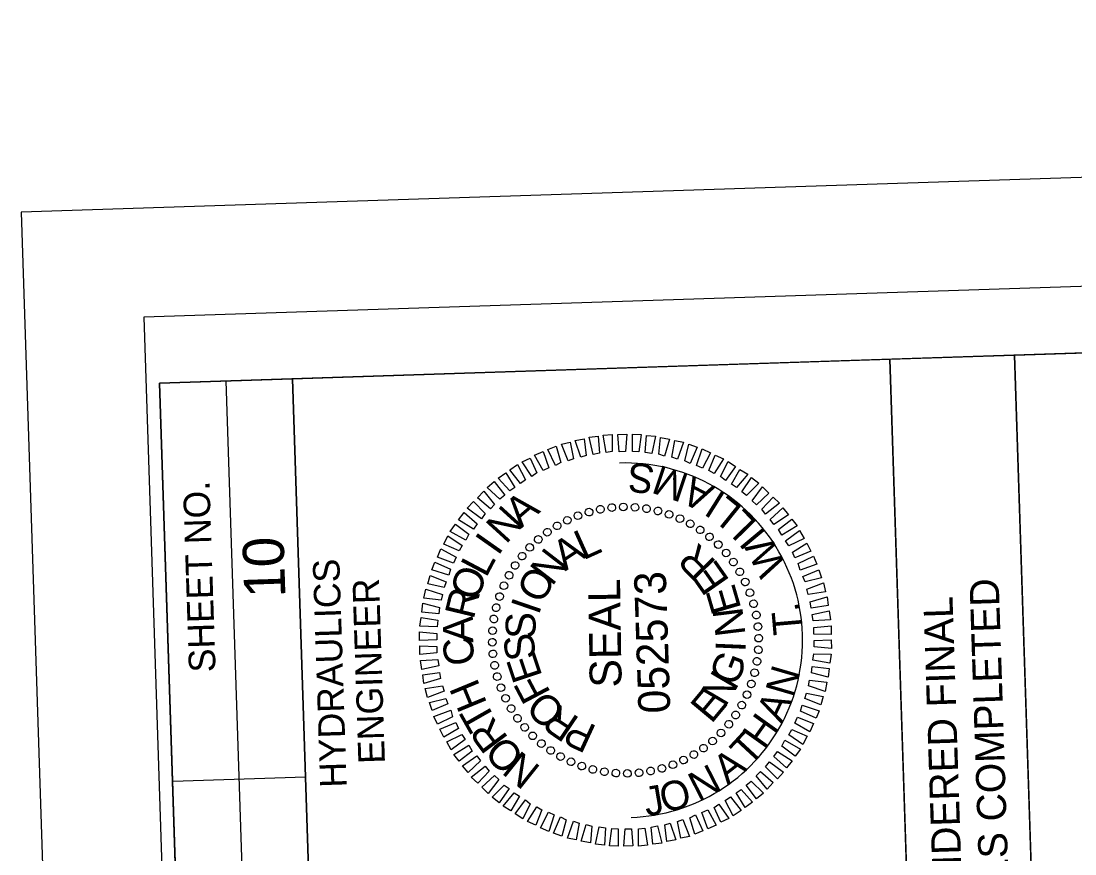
# Model space of a CAD drawing. Extents: x 1627314 to 1628469, y 762309 to 764247.
# Drawn here: x 1627314.2 to 1627512.6, y 763887.6 to 764044.4 of the extents above; entities that cross this region are included whole.
import ezdxf

# ---------------------------------------------------------------- set-up
doc = ezdxf.new("R2010")
doc.units = 0
for name, color, linetype in [('Old_Level_2', 7, 'Continuous'), ('Old_Level_58', 7, 'Continuous'), ('Scratch_Level_0', 7, 'Continuous'), ('Sheet Data Field CELL', 7, 'Continuous'), ('Sheet Plot Border Inside CELL', 7, 'Continuous'), ('Sheet Plot Border Outside CELL', 7, 'Continuous'), ('Sheet Professional Seal CELL', 7, 'Continuous'), ('Sheet Profile CELL', 7, 'Continuous'), ('Sheet Profile Grid Major CELL', 7, 'Continuous'), ('Sheet Profile Grid Minor CELL', 7, 'Continuous'), ('Sheet Sticker Exception Certification CELL', 7, 'Continuous')]:
    doc.layers.add(name, color=color, linetype=linetype)

msp = doc.modelspace()

# ---------------------------------------------------------------- linework, layer by layer
at = {"layer": 'Old_Level_2'}
msp.add_lwpolyline([(1627507.79, 763781.61), (1627501.25, 763981.49), (1627565.16, 763983.58), (1627571.7, 763783.7)], close=True, dxfattribs=at)
at = {"layer": 'Scratch_Level_0'}
msp.add_arc((1627428, 763927.84), 33.36, 271.8735, 91.8735, dxfattribs=at)
at = {"layer": 'Sheet Plot Border Inside CELL'}
msp.add_lwpolyline([(1628446.34, 762357.53), (1628391.86, 764023.14), (1627337.33, 763988.65), (1627391.81, 762323.04)], close=True, dxfattribs=at)
at = {"layer": 'Sheet Plot Border Outside CELL'}
msp.add_lwpolyline([(1628469.21, 762345.27), (1628413.63, 764044.37), (1627314.22, 764008.4), (1627369.79, 762309.31)], close=True, dxfattribs=at)
at = {"layer": 'Sheet Professional Seal CELL'}
for p, q in [((1627421.1, 763951.98), (1627421.1, 763951.98)), ((1627423.29, 763952.45), (1627423.29, 763952.45)), ((1627425.43, 763952.82), (1627425.43, 763952.82)), ((1627427.62, 763952.94), (1627427.62, 763952.94)), ((1627429.83, 763952.86), (1627429.83, 763952.86)), ((1627431.99, 763952.58), (1627431.99, 763952.58)), ((1627434.1, 763952.2), (1627434.1, 763952.2)), ((1627436.22, 763951.57), (1627436.22, 763951.57)), ((1627417.05, 763950.44), (1627417.05, 763950.44)), ((1627419.02, 763951.31), (1627419.02, 763951.31)), ((1627438.25, 763950.74), (1627438.25, 763950.74)), ((1627440.23, 763949.8), (1627440.23, 763949.8)), ((1627413.27, 763948.17), (1627413.27, 763948.17)), ((1627415.13, 763949.38), (1627415.13, 763949.38)), ((1627442.07, 763948.61), (1627442.07, 763948.61)), ((1627411.56, 763946.86), (1627411.56, 763946.86)), ((1627443.87, 763947.32), (1627443.87, 763947.32)), ((1627445.47, 763945.87), (1627445.47, 763945.87)), ((1627408.52, 763943.71), (1627408.52, 763943.71)), ((1627409.96, 763945.31), (1627409.96, 763945.31)), ((1627447.02, 763944.27), (1627447.02, 763944.27)), ((1627407.22, 763941.92), (1627407.22, 763941.92)), ((1627448.33, 763942.56), (1627448.33, 763942.56)), ((1627406.03, 763940.08), (1627406.03, 763940.08)), ((1627449.54, 763940.7), (1627449.54, 763940.7)), ((1627405.1, 763938.1), (1627405.1, 763938.1)), ((1627450.6, 763938.78), (1627450.6, 763938.78)), ((1627404.26, 763936.07), (1627404.26, 763936.07)), ((1627451.46, 763936.81), (1627451.46, 763936.81)), ((1627403.63, 763933.95), (1627403.63, 763933.95)), ((1627452.13, 763934.73), (1627452.13, 763934.73)), ((1627403.25, 763931.83), (1627403.25, 763931.83)), ((1627452.6, 763932.55), (1627452.6, 763932.55)), ((1627402.97, 763929.67), (1627402.97, 763929.67)), ((1627452.98, 763930.41), (1627452.98, 763930.41)), ((1627428, 763927.84), (1627428, 763927.84)), ((1627453.1, 763928.21), (1627453.1, 763928.21)), ((1627402.89, 763927.47), (1627402.89, 763927.47)), ((1627453.02, 763926.01), (1627453.02, 763926.01)), ((1627403.02, 763925.27), (1627403.02, 763925.27)), ((1627452.74, 763923.85), (1627452.74, 763923.85)), ((1627403.39, 763923.13), (1627403.39, 763923.13)), ((1627452.36, 763921.73), (1627452.36, 763921.73)), ((1627403.86, 763920.95), (1627403.86, 763920.95)), ((1627404.53, 763918.87), (1627404.53, 763918.87)), ((1627451.73, 763919.61), (1627451.73, 763919.61)), ((1627405.39, 763916.89), (1627405.39, 763916.89)), ((1627450.89, 763917.58), (1627450.89, 763917.58)), ((1627406.45, 763914.98), (1627406.45, 763914.98)), ((1627448.77, 763913.76), (1627448.77, 763913.76)), ((1627449.96, 763915.6), (1627449.96, 763915.6)), ((1627407.67, 763913.12), (1627407.67, 763913.12)), ((1627447.47, 763911.97), (1627447.47, 763911.97)), ((1627408.97, 763911.41), (1627408.97, 763911.41)), ((1627410.53, 763909.81), (1627410.53, 763909.81)), ((1627446.03, 763910.37), (1627446.03, 763910.37)), ((1627412.12, 763908.36), (1627412.12, 763908.36)), ((1627444.43, 763908.82), (1627444.43, 763908.82)), ((1627413.92, 763907.07), (1627413.92, 763907.07)), ((1627415.76, 763905.88), (1627415.76, 763905.88)), ((1627440.86, 763906.3), (1627440.86, 763906.3)), ((1627442.72, 763907.51), (1627442.72, 763907.51)), ((1627417.74, 763904.94), (1627417.74, 763904.94)), ((1627419.77, 763904.11), (1627419.77, 763904.11)), ((1627436.97, 763904.37), (1627436.97, 763904.37)), ((1627438.94, 763905.23), (1627438.94, 763905.23)), ((1627421.89, 763903.48), (1627421.89, 763903.48)), ((1627424, 763903.09), (1627424, 763903.09)), ((1627426.16, 763902.82), (1627426.16, 763902.82)), ((1627428.37, 763902.74), (1627428.37, 763902.74)), ((1627430.56, 763902.86), (1627430.56, 763902.86)), ((1627432.7, 763903.23), (1627432.7, 763903.23)), ((1627434.89, 763903.7), (1627434.89, 763903.7))]:
    msp.add_line(p, q, dxfattribs=at)
for points in [[(1627419.57, 763962.28), (1627418.51, 763965.4), (1627420.2, 763965.75), (1627420.6, 763962.62)], [(1627421.95, 763962.81), (1627421.14, 763966.03), (1627422.84, 763966.24), (1627423.14, 763963.05)], [(1627424.34, 763963.19), (1627423.83, 763966.42), (1627425.53, 763966.58), (1627425.53, 763963.33)], [(1627426.84, 763963.32), (1627426.58, 763966.56), (1627428.28, 763966.62), (1627428.03, 763963.36)], [(1627429.34, 763963.35), (1627429.33, 763966.6), (1627430.98, 763966.56), (1627430.54, 763963.29)], [(1627431.74, 763963.18), (1627431.94, 763966.39), (1627433.64, 763966.24), (1627432.95, 763962.97)], [(1627434.3, 763962.86), (1627434.6, 763965.97), (1627436.31, 763965.68), (1627435.37, 763962.5)], [(1627436.72, 763962.29), (1627437.27, 763965.41), (1627438.93, 763965.12), (1627437.79, 763961.93)], [(1627412.49, 763959.75), (1627410.9, 763962.65), (1627412.48, 763963.35), (1627413.58, 763960.28)], [(1627414.81, 763960.72), (1627413.41, 763963.73), (1627414.95, 763964.33), (1627415.85, 763961.26)], [(1627417.19, 763961.6), (1627415.93, 763964.76), (1627417.57, 763965.12), (1627418.22, 763961.99)], [(1627439.15, 763961.62), (1627439.95, 763964.75), (1627441.52, 763964.15), (1627440.21, 763961.11)], [(1627441.38, 763960.69), (1627442.43, 763963.83), (1627444, 763963.13), (1627442.49, 763960.23)], [(1627410.38, 763958.68), (1627408.54, 763961.42), (1627410.07, 763962.12), (1627411.31, 763959.31)], [(1627443.71, 763959.77), (1627444.87, 763962.66), (1627446.44, 763961.96), (1627444.68, 763959.2)], [(1627445.9, 763958.64), (1627447.31, 763961.49), (1627448.74, 763960.53), (1627446.82, 763957.87)], [(1627408.22, 763957.31), (1627406.24, 763959.89), (1627407.7, 763960.89), (1627409.2, 763958.04)], [(1627447.95, 763957.21), (1627449.56, 763959.96), (1627451.04, 763959.06), (1627448.92, 763956.59)], [(1627404.32, 763954.38), (1627401.99, 763956.6), (1627403.31, 763957.7), (1627405.29, 763955.11)], [(1627406.22, 763955.94), (1627404.04, 763958.32), (1627405.45, 763959.32), (1627407.15, 763956.57)], [(1627449.89, 763955.77), (1627451.76, 763958.43), (1627453.09, 763957.37), (1627450.82, 763955.1)], [(1627402.57, 763952.57), (1627400.15, 763954.64), (1627401.31, 763955.88), (1627403.35, 763953.35)], [(1627451.85, 763954.08), (1627453.82, 763956.7), (1627455.01, 763955.49), (1627452.68, 763953.31)], [(1627400.88, 763950.71), (1627398.22, 763952.68), (1627399.38, 763953.92), (1627401.6, 763951.69)], [(1627453.65, 763952.49), (1627455.78, 763954.76), (1627457.02, 763953.6), (1627454.38, 763951.56)], [(1627399.4, 763948.76), (1627396.59, 763950.52), (1627397.64, 763951.86), (1627400.06, 763949.74)], [(1627455.27, 763950.54), (1627457.6, 763952.77), (1627458.69, 763951.45), (1627455.95, 763949.61)], [(1627397.96, 763946.67), (1627395.01, 763948.32), (1627396.02, 763949.65), (1627398.53, 763947.79)], [(1627456.83, 763948.69), (1627459.32, 763950.62), (1627460.31, 763949.36), (1627457.46, 763947.61)], [(1627396.68, 763944.67), (1627393.79, 763945.93), (1627394.59, 763947.46), (1627397.25, 763945.64)], [(1627458.15, 763946.53), (1627460.79, 763948.47), (1627461.64, 763946.95), (1627458.78, 763945.6)], [(1627459.42, 763944.42), (1627462.17, 763946.12), (1627462.92, 763944.59), (1627459.91, 763943.34)], [(1627395.6, 763942.34), (1627392.62, 763943.49), (1627393.26, 763945.06), (1627396.12, 763943.45)], [(1627460.54, 763942.26), (1627463.4, 763943.65), (1627464.05, 763942.17), (1627460.88, 763941.02)], [(1627394.73, 763940.06), (1627391.54, 763941.1), (1627392.1, 763942.52), (1627395.04, 763941.22)], [(1627393.9, 763937.78), (1627390.78, 763938.43), (1627391.23, 763939.99), (1627394.22, 763938.84)], [(1627461.42, 763939.84), (1627464.38, 763941.08), (1627464.88, 763939.55), (1627461.81, 763938.8)], [(1627462.15, 763937.46), (1627465.26, 763938.61), (1627465.67, 763936.92), (1627462.43, 763936.42)], [(1627393.33, 763935.36), (1627390.07, 763935.75), (1627390.41, 763937.46), (1627393.55, 763936.42)], [(1627462.78, 763935.08), (1627465.95, 763935.98), (1627466.15, 763934.34), (1627462.97, 763933.88)], [(1627392.86, 763932.79), (1627389.65, 763933.14), (1627389.85, 763934.79), (1627392.98, 763934)], [(1627392.54, 763930.38), (1627389.29, 763930.47), (1627389.53, 763932.13), (1627392.7, 763931.59)], [(1627463.16, 763932.69), (1627466.34, 763933.34), (1627466.59, 763931.65), (1627463.34, 763931.5)], [(1627463.49, 763930.2), (1627466.73, 763930.56), (1627466.73, 763928.91), (1627463.48, 763929)], [(1627392.48, 763927.88), (1627389.23, 763927.77), (1627389.22, 763929.42), (1627392.49, 763929.08)], [(1627463.52, 763927.8), (1627466.76, 763927.91), (1627466.77, 763926.26), (1627463.51, 763926.6)], [(1627392.5, 763925.48), (1627389.26, 763925.12), (1627389.26, 763926.77), (1627392.51, 763926.68)], [(1627392.84, 763922.99), (1627389.66, 763922.33), (1627389.4, 763924.02), (1627392.65, 763924.18)], [(1627463.45, 763925.3), (1627466.7, 763925.2), (1627466.46, 763923.54), (1627463.29, 763924.09)], [(1627393.21, 763920.6), (1627390.04, 763919.69), (1627389.84, 763921.34), (1627393.02, 763921.79)], [(1627463.13, 763922.88), (1627466.34, 763922.54), (1627466.14, 763920.88), (1627463.02, 763921.68)], [(1627462.66, 763920.32), (1627465.92, 763919.92), (1627465.58, 763918.21), (1627462.44, 763919.26)], [(1627393.84, 763918.22), (1627390.73, 763917.06), (1627390.32, 763918.75), (1627393.56, 763919.26)], [(1627462.09, 763917.9), (1627465.21, 763917.25), (1627464.76, 763915.68), (1627461.77, 763916.84)], [(1627394.57, 763915.84), (1627391.61, 763914.59), (1627391.11, 763916.13), (1627394.19, 763916.88)], [(1627395.45, 763913.42), (1627392.59, 763912.02), (1627391.95, 763913.5), (1627395.11, 763914.66)], [(1627461.26, 763915.62), (1627464.45, 763914.57), (1627463.89, 763913.15), (1627460.95, 763914.46)], [(1627396.57, 763911.25), (1627393.82, 763909.56), (1627393.07, 763911.09), (1627396.09, 763912.34)], [(1627460.39, 763913.34), (1627463.38, 763912.19), (1627462.73, 763910.61), (1627459.87, 763912.22)], [(1627397.84, 763909.14), (1627395.2, 763907.21), (1627394.35, 763908.73), (1627397.21, 763910.07)], [(1627459.31, 763911), (1627462.21, 763909.75), (1627461.4, 763908.22), (1627458.74, 763910.03)], [(1627399.16, 763906.98), (1627396.67, 763905.05), (1627395.68, 763906.32), (1627398.53, 763908.06)], [(1627458.03, 763909.01), (1627460.98, 763907.36), (1627459.98, 763906.02), (1627457.46, 763907.89)], [(1627400.72, 763905.13), (1627398.39, 763902.91), (1627397.3, 763904.22), (1627400.04, 763906.06)], [(1627456.6, 763906.91), (1627459.4, 763905.15), (1627458.35, 763903.82), (1627455.93, 763905.94)], [(1627402.34, 763903.19), (1627400.21, 763900.92), (1627398.97, 763902.08), (1627401.61, 763904.11)], [(1627455.11, 763904.96), (1627457.77, 763903), (1627456.61, 763901.76), (1627454.39, 763903.99)], [(1627404.14, 763901.59), (1627402.18, 763898.98), (1627400.99, 763900.19), (1627403.32, 763902.37)], [(1627453.42, 763903.11), (1627455.84, 763901.03), (1627454.68, 763899.8), (1627452.64, 763902.33)], [(1627406.1, 763899.91), (1627404.23, 763897.25), (1627402.9, 763898.3), (1627405.17, 763900.58)], [(1627451.68, 763901.3), (1627454, 763899.07), (1627452.68, 763897.98), (1627450.7, 763900.57)], [(1627408.05, 763898.47), (1627406.43, 763895.72), (1627404.95, 763896.62), (1627407.07, 763899.09)], [(1627447.77, 763898.37), (1627449.76, 763895.78), (1627448.29, 763894.78), (1627446.79, 763897.64)], [(1627449.78, 763899.74), (1627451.95, 763897.36), (1627450.54, 763896.36), (1627448.85, 763899.1)], [(1627410.09, 763897.04), (1627408.69, 763894.19), (1627407.25, 763895.14), (1627409.17, 763897.81)], [(1627412.28, 763895.91), (1627411.12, 763893.02), (1627409.55, 763893.72), (1627411.31, 763896.48)], [(1627443.5, 763895.93), (1627445.09, 763893.03), (1627443.51, 763892.33), (1627442.41, 763895.39)], [(1627445.61, 763897), (1627447.45, 763894.26), (1627445.93, 763893.56), (1627444.68, 763896.37)], [(1627414.61, 763894.98), (1627413.56, 763891.85), (1627411.99, 763892.55), (1627413.5, 763895.45)], [(1627416.84, 763894.06), (1627416.05, 763890.93), (1627414.48, 763891.53), (1627415.78, 763894.57)], [(1627438.81, 763894.07), (1627440.06, 763890.91), (1627438.42, 763890.56), (1627437.77, 763893.69)], [(1627441.18, 763894.95), (1627442.58, 763891.95), (1627441.05, 763891.35), (1627440.14, 763894.42)], [(1627419.27, 763893.38), (1627418.72, 763890.26), (1627417.06, 763890.56), (1627418.2, 763893.75)], [(1627421.69, 763892.81), (1627421.39, 763889.7), (1627419.68, 763890), (1627420.62, 763893.18)], [(1627424.25, 763892.5), (1627424.05, 763889.29), (1627422.35, 763889.43), (1627423.04, 763892.71)], [(1627426.66, 763892.33), (1627426.66, 763889.07), (1627425.01, 763889.12), (1627425.45, 763892.39)], [(1627429.16, 763892.36), (1627429.41, 763889.11), (1627427.71, 763889.06), (1627427.96, 763892.32)], [(1627431.65, 763892.49), (1627432.16, 763889.25), (1627430.46, 763889.1), (1627430.46, 763892.35)], [(1627434.04, 763892.87), (1627434.85, 763889.64), (1627433.15, 763889.44), (1627432.85, 763892.63)], [(1627436.43, 763893.4), (1627437.48, 763890.28), (1627435.79, 763889.92), (1627435.39, 763893.06)]]:
    msp.add_lwpolyline(points, close=True, dxfattribs=at)
for centre, major_axis in [((1627425.43, 763952.79), (-0.074, 0.716)), ((1627427.61, 763952.92), (-0.011, 0.72)), ((1627429.8, 763952.85), (0.052, 0.718)), ((1627419.06, 763951.27), (-0.257, 0.673)), ((1627421.14, 763951.96), (-0.197, 0.693)), ((1627423.26, 763952.47), (-0.136, 0.707)), ((1627431.97, 763952.6), (0.114, 0.711)), ((1627434.12, 763952.16), (0.176, 0.698)), ((1627436.21, 763951.53), (0.236, 0.68)), ((1627438.25, 763950.73), (0.294, 0.657)), ((1627415.13, 763949.36), (-0.369, 0.618)), ((1627417.05, 763950.4), (-0.314, 0.648)), ((1627440.2, 763949.75), (0.35, 0.629)), ((1627411.58, 763946.8), (-0.471, 0.544)), ((1627413.3, 763948.16), (-0.422, 0.583)), ((1627442.07, 763948.6), (0.404, 0.596)), ((1627443.82, 763947.29), (0.454, 0.559)), ((1627409.99, 763945.3), (-0.517, 0.501)), ((1627445.46, 763945.84), (0.501, 0.517)), ((1627408.54, 763943.66), (-0.559, 0.454)), ((1627446.96, 763944.25), (0.544, 0.471)), ((1627407.23, 763941.91), (-0.596, 0.404)), ((1627448.32, 763942.54), (0.583, 0.422)), ((1627449.52, 763940.71), (0.618, 0.369)), ((1627406.09, 763940.05), (-0.629, 0.35)), ((1627450.56, 763938.78), (0.648, 0.314)), ((1627405.11, 763938.09), (-0.657, 0.294)), ((1627451.43, 763936.77), (0.673, 0.257)), ((1627404.3, 763936.06), (-0.68, 0.236)), ((1627403.67, 763933.96), (-0.698, 0.176)), ((1627452.12, 763934.7), (0.693, 0.197)), ((1627403.23, 763931.82), (-0.711, 0.114)), ((1627452.63, 763932.57), (0.707, 0.136)), ((1627402.98, 763929.64), (-0.718, 0.052)), ((1627452.94, 763930.4), (0.716, 0.074)), ((1627402.92, 763927.46), (-0.72, -0.011)), ((1627453.07, 763928.22), (0.72, 0.011)), ((1627403.05, 763925.27), (-0.716, -0.074)), ((1627453.01, 763926.03), (0.718, -0.052)), ((1627403.37, 763923.11), (-0.707, -0.136)), ((1627452.76, 763923.86), (0.711, -0.114)), ((1627403.87, 763920.98), (-0.693, -0.197)), ((1627452.32, 763921.72), (0.698, -0.176)), ((1627404.56, 763918.9), (-0.673, -0.257)), ((1627451.69, 763919.62), (0.68, -0.236)), ((1627405.43, 763916.89), (-0.648, -0.314)), ((1627450.88, 763917.59), (0.657, -0.294)), ((1627406.47, 763914.97), (-0.618, -0.369)), ((1627449.9, 763915.63), (0.629, -0.35)), ((1627407.67, 763913.14), (-0.583, -0.422)), ((1627448.76, 763913.77), (0.596, -0.404)), ((1627409.03, 763911.43), (-0.544, -0.471)), ((1627447.45, 763912.01), (0.559, -0.454)), ((1627410.53, 763909.84), (-0.501, -0.517)), ((1627446, 763910.38), (0.517, -0.501)), ((1627412.17, 763908.38), (-0.454, -0.559)), ((1627413.93, 763907.08), (-0.404, -0.596)), ((1627442.69, 763907.52), (0.422, -0.583)), ((1627444.41, 763908.87), (0.471, -0.544)), ((1627415.79, 763905.93), (-0.35, -0.629)), ((1627438.94, 763905.27), (0.314, -0.648)), ((1627440.87, 763906.31), (0.369, -0.618)), ((1627417.74, 763904.95), (-0.294, -0.657)), ((1627419.78, 763904.14), (-0.236, -0.68)), ((1627421.87, 763903.52), (-0.176, -0.698)), ((1627424.02, 763903.08), (-0.114, -0.711)), ((1627432.73, 763903.21), (0.136, -0.707)), ((1627434.86, 763903.71), (0.197, -0.693)), ((1627436.93, 763904.4), (0.257, -0.673)), ((1627426.19, 763902.82), (-0.052, -0.718)), ((1627428.38, 763902.76), (0.011, -0.72)), ((1627430.56, 763902.89), (0.074, -0.716))]:
    msp.add_ellipse(centre, major_axis=major_axis, ratio=0.999708, dxfattribs=at)
at = {"layer": 'Sheet Profile CELL'}
for p, q in [((1627359.37, 763776.71), (1627352.83, 763976.65)), ((1627342.78, 763901.28), (1627367.77, 763902.1))]:
    msp.add_line(p, q, dxfattribs=at)
for points in [[(1627340.28, 763976.24), (1627389.32, 762477.04), (1628438.76, 762511.37), (1628389.72, 764010.57)], [(1627368.59, 763877.11), (1627365.32, 763977.06), (1627477.76, 763980.74), (1627481.03, 763880.79)], [(1627346.82, 763776.3), (1627340.28, 763976.24), (1627365.32, 763977.06), (1627371.86, 763777.12)]]:
    msp.add_lwpolyline(points, close=True, dxfattribs=at)
at = {"layer": 'Sheet Profile Grid Major CELL'}
msp.add_lwpolyline([(1627566.8, 763933.62), (1627841.65, 763942.61), (1627840.02, 763992.59), (1627490.2, 763981.14)], dxfattribs=at)
at = {"layer": 'Sheet Sticker Exception Certification CELL'}
for p, q in [((1627477.77, 763980.72), (1627501.26, 763981.49)), ((1627477.77, 763980.72), (1627501.26, 763981.49)), ((1627501.25, 763981.49), (1627507.79, 763781.56)), ((1627501.25, 763981.49), (1627507.79, 763781.56)), ((1627484.3, 763780.79), (1627477.76, 763980.72)), ((1627484.3, 763780.79), (1627477.76, 763980.72))]:
    msp.add_line(p, q, dxfattribs=at)

# ---------------------------------------------------------------- texts
at = {"layer": 'Old_Level_58'}
for s, rotation, p in [('S', 173.0617, (1627433.71, 763960.75)), ('M', 161.4413, (1627440.22, 763958.93)), ('A', 152.311, (1627445, 763956.6)), ('I', 147.846, (1627447.18, 763955.18)), ('L', 141.0913, (1627450.27, 763952.74)), ('L', 134.3366, (1627453.04, 763949.94)), ('I', 129.8716, (1627454.69, 763947.93)), ('W', 117.321, (1627458.41, 763941.65)), ('.', 102.2517, (1627460.96, 763933.26)), ('T', 95.0104, (1627461.38, 763929.07)), ('N', 73.7445, (1627459.55, 763916.87)), ('A', 64.6142, (1627457.41, 763912.01)), ('H', 54.4249, (1627454.15, 763907.05)), ('T', 47.1836, (1627451.32, 763903.92)), ('A', 38.0533, (1627447.23, 763900.52)), ('N', 27.1771, (1627441.73, 763897.38)), ('J', 9.715, (1627431.96, 763894.67)), ('O', 15.528, (1627435.3, 763895.24))]:
    msp.add_text(s, height=5.5, rotation=rotation, dxfattribs=at).set_placement(p)
at = {"layer": 'Sheet Data Field CELL'}
msp.add_text('10', height=7.75, rotation=91.8735, dxfattribs=at).set_placement((1627364, 763935.91))
at = {"layer": 'Sheet Professional Seal CELL'}
for s, height, rotation, p in [('A', 5.64, 40.4906, (1627408.35, 763948.81)), ('N', 5.64, 47.6924, (1627405.5, 763945.76)), ('I', 5.64, 54.8936, (1627404.02, 763943.56)), ('L', 5.64, 24.2743, (1627420.05, 763942.84)), ('A', 5.64, 33.6337, (1627416.67, 763940.77)), ('R', 5.64, 134.3549, (1627445.28, 763942.51)), ('N', 5.64, 52.3501, (1627414.16, 763937.84)), ('L', 5.64, 62.0943, (1627401.75, 763939.44)), ('E', 5.64, 124.9976, (1627447.74, 763939.04)), ('O', 5.64, 69.2946, (1627400.05, 763934.98)), ('O', 5.64, 61.707, (1627412.27, 763934.43)), ('SEAL', 5.998, 90.8735, (1627427.29, 763918.96)), ('E', 5.64, 106.2852, (1627449.86, 763933.81)), ('R', 5.64, 76.4946, (1627399.41, 763931.61)), ('I', 5.64, 71.0631, (1627411.64, 763932.41)), ('N', 5.64, 96.9299, (1627450.62, 763928.88)), ('A', 5.64, 90.8938, (1627399.34, 763927.4)), ('S', 5.64, 89.7739, (1627411.08, 763928.09)), ('C', 5.64, 98.0933, (1627399.77, 763923.46)), ('S', 5.64, 99.1291, (1627411.25, 763924.49)), ('I', 5.64, 87.5747, (1627450.58, 763925.53)), ('E', 5.64, 108.4845, (1627412.41, 763921.08)), ('G', 5.64, 68.8637, (1627448.9, 763918.92)), ('N', 5.64, 59.5074, (1627446.77, 763915.05)), ('H', 5.64, 112.4929, (1627402.02, 763915.93)), ('F', 5.64, 117.8405, (1627414.01, 763917.93)), ('E', 5.64, 50.1504, (1627444.17, 763911.96)), ('O', 5.64, 136.5547, (1627417.07, 763914.72)), ('R', 5.64, 145.9131, (1627419.57, 763913.06)), ('T', 5.64, 119.6932, (1627403.78, 763912.74)), ('R', 5.64, 126.894, (1627406.09, 763909.41)), ('P', 5.64, 155.2724, (1627422.83, 763911.56)), ('O', 5.64, 134.0952, (1627409.3, 763906.07)), ('N', 5.64, 141.297, (1627412.27, 763903.86))]:
    msp.add_text(s, height=height, rotation=rotation, dxfattribs=at).set_placement(p)
at = {"layer": 'Sheet Profile CELL'}
for s, p in [('SHEET NO.', (1627350.85, 763921.87)), ('HYDRAULICS', (1627375.53, 763900.16)), ('ENGINEER', (1627382.73, 763904.65))]:
    msp.add_text(s, height=5, rotation=91.8735, dxfattribs=at).set_placement(p)
at = {"layer": 'Sheet Profile Grid Minor CELL'}
msp.add_text('052573', height=5.998, rotation=91.8735, dxfattribs=at).set_placement((1627436.46, 763914.15))
at = {"layer": 'Sheet Sticker Exception Certification CELL'}
for s, p in [('UNLESS ALL SIGNATURES COMPLETED', (1627502.91, 763797.41)), ('UNLESS ALL SIGNATURES COMPLETED', (1627502.91, 763797.41)), ('DOCUMENT NOT CONSIDERED FINAL', (1627493.95, 763802.19)), ('DOCUMENT NOT CONSIDERED FINAL', (1627493.95, 763802.19))]:
    msp.add_text(s, height=5.5, rotation=91.8735, dxfattribs=at).set_placement(p)

doc.saveas('drawing.dxf')
